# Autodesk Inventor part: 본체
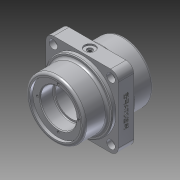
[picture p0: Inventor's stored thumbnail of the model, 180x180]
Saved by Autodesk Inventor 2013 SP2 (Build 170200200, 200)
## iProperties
Created: 2023-10
Part Number: 본체
Material: 알루미늄 6061
Document SubType Name: Modeling
Designer: i
Density: 2.71 g/cm^3
Mass: 949.289 g
Surface Area: 536.974 cm^2
Volume: 350.291 cm^3
Author: i
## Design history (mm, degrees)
sketch "스케치1"
  geometry: L1 (-47, 47)-(47, 47); L2 (47, 47)-(47, -47); L3 (47, -47)-(-47, -47); L4 (-47, -47)-(-47, 47); L5 (-47, 47)-(47, -47); L6 (47, 47)-(-47, -47); 1 further point
  constraints: 12 end point, 2 midpoint, 2 parallel, 1 horizontal, 1 perpendicular
  dimensions: "d0" = 94 distance of L2.end L3.end; "d1" = 94 distance of L1.end L2.end
extrude "돌출1" new body sketch "스케치1" stored distance "d2" = 20; taper "d3" = 0 deg
sketch "스케치2"
  geometry: C1 r 44 at (0, 0); 1 further point
  constraints: 1 centre point, 1 coincident
  dimensions: "d4" = 88 diameter of C1
extrude "돌출2" join sketch "스케치2" distance "d6" = 5; taper "d7" = 0 deg
sketch "스케치3"
  geometry: C1 r 44 at (0, 0) reference; C2 r 38 at (0, 0)
  constraints: 1 centre point, 1 coincident
  dimensions: "d8" = 76 diameter of C2
extrude "돌출3" join sketch "스케치3" distance "d9" = 30; taper "d10" = 0 deg
sketch "스케치4"
  geometry: L1 (38, 45)-(-38, 45) reference; L2 (38, -45)-(-38, -45) reference; L3 (0, 45)-(0, -45); L4 (33, 45)-(33, 41); L5 (33, 41)-(23.5, 41); L6 (23.5, 41)-(23.5, 24); L7 (23.5, 24)-(20.5, 24); L8 (20.5, 24)-(20.5, -24); L9 (20.5, -24)-(23.5, -24); L10 (23.5, -24)-(23.5, -41); L11 (23.5, -41)-(33, -41); L12 (33, -41)-(33, -45); 1 further point
  constraints: 20 end point, 7 parallel, 3 collinear, 2 midpoint, 2 perpendicular, 2 point on line
  dimensions: "d11" = 66 diameter of L4 L3; "d13" = 4 distance of L4.start L4.end; "d14" = 47 diameter of L6 L3; "d15" = 17 distance of L5.end L6.end; "d16" = 17 distance of L9.end L10.end; "d17" = 41 diameter of L8 L3
revolve "회전1" sketch "스케치4" stored, may be unused: angle "d18" = 90 deg
fillet "모깎기1" dims "d19" = 10
sketch "스케치11" dims "d63" = 106
  geometry: L1 (0, 0)-(47, 47); L2 (0, 0)-(66.468, 0); C1 r 44 at (0, 0) reference; 1 further point
  constraints: 4 end point, 1 coincident, 1 equal length, 1 horizontal, 1 point on line, 3 other
  dimensions: "d64" = 45 deg angle of L2 L1; "d65" = 47 horizontal distance of L1.start L1.end
hole "구멍6" sketch "스케치11" at (37.477, 37.477) diameter "d66" = 6.6; stored, may be unused: countersink angle "d70" = 90 deg, drill point angle "d72" = 118 deg; dims "d67" = 8, "d68" = 11, "d69" = 7, "d71" = 10
sketch "스케치7"
  geometry: 2 further points
  constraints: 1 coincident
hole "구멍3" sketch "스케치7" at (37, 10) diameter "d34" = 5.188; stored, may be unused: countersink angle "d38" = 90 deg, drill point angle "d40" = 118 deg; dims "d35" = 16, "d36" = 7, "d37" = 4, "d39" = 8
sketch "스케치8"
  geometry: C1 r 3.5 at (37, 10) reference; 1 further point
  constraints: 1 coincident
hole "구멍4" sketch "스케치8" at (37, 10) diameter "d41" = 14; stored, may be unused: countersink angle "d45" = 90 deg, drill point angle "d47" = 0 deg; dims "d42" = 16, "d43" = 7, "d44" = 4, "d46" = 2
sketch "스케치9"
  geometry: L1 (-20, 0)-(-20, 74) reference; 2 further points
  constraints: 1 coincident, 1 other
  dimensions: "d48" = 10 distance from line of point (-10, 37) L1
feature "엠보싱1" sketch "스케치9" dims "d0" = 94, "d1" = 94, "d49" = 0.5, "d50" = 0
sketch "스케치10"
  geometry: C1 r 33 at (0, 0) reference; 1 further point
  constraints: 1 vertical alignment
  dimensions: "d51" = 27 distance of C1.centre point (0, 27)
hole "구멍5" sketch "스케치10" at (0, 27) diameter "d52" = 3.242; stored, may be unused: countersink angle "d56" = 90 deg, drill point angle "d58" = 118 deg; dims "d53" = 8, "d54" = 7, "d55" = 4, "d57" = 10
chamfer "모따기1" distance "d83" = 1; stored, may be unused: second distance "d84" = 2, angle "d85" = 45 deg
fillet "모깎기2" dims "d89" = 1
fillet "모깎기3" dims "d90" = 3
chamfer "모따기3" distance "d91" = 1; stored, may be unused: second distance "d92" = 2, angle "d93" = 45 deg
sketch "스케치13"
  geometry: C1 r 3.3 at (-37.477, 37.477) reference; C2 r 44 at (0, 0) reference; C3 r 53 at (0, 0); 1 further point
  constraints: 2 coincident, 1 centre point
  dimensions: "d94" = 106 diameter of C3
hole "구멍8" sketch "스케치13" at (-37.477, 37.477) diameter "d95" = 6.6; stored, may be unused: countersink angle "d99" = 90 deg, drill point angle "d101" = 118 deg; dims "d96" = 8, "d97" = 11, "d98" = 7, "d100" = 10
node "솔리드1"
mirror "대칭1"
pattern_circular "원형 패턴2" dims angle "d81" = 360 deg
pattern_circular "원형 패턴1" dims angle "d60" = 360 deg
mirror "대칭2"
pattern_circular "원형 패턴3" dims angle "d103" = 360 deg
